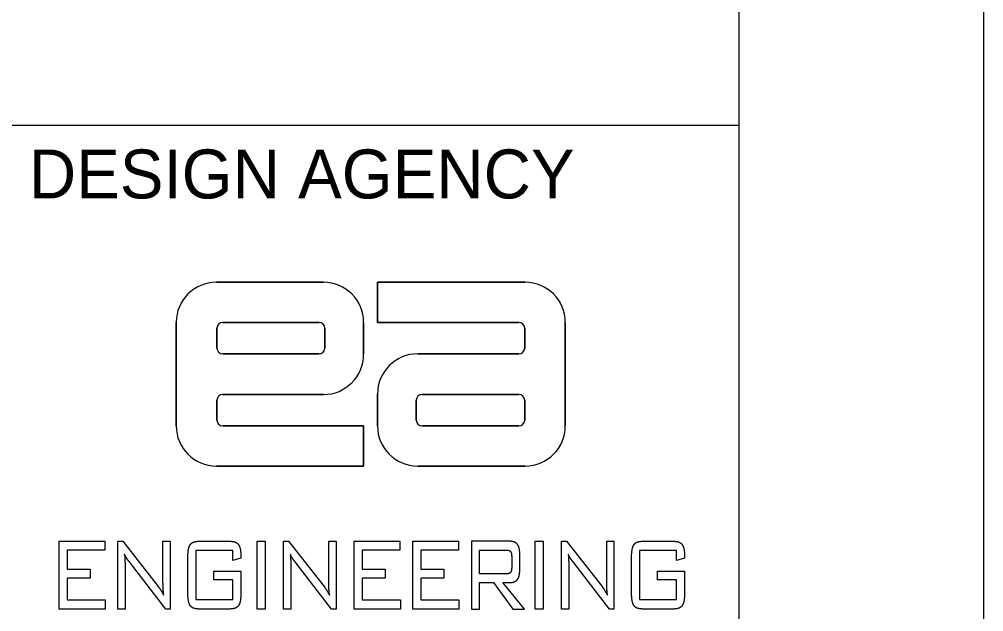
# Model space of a CAD drawing. Extents: x -15.1 to 34, y -7.8 to 43.8.
# Drawn here: x 32.03 to 34, y 3.506 to 4.716 of the extents above; entities that cross this region are included whole.
import ezdxf

# ---------------------------------------------------------------- set-up
doc = ezdxf.new("R2010")
doc.units = 0
for name, color, linetype in [('SH_Border', 7, 'Continuous'), ('SH_Cut_Line', 7, 'Continuous'), ('SH_Data', 7, 'Continuous'), ('TX_X_20', 7, 'Continuous')]:
    doc.layers.add(name, color=color, linetype=linetype)

msp = doc.modelspace()

# ---------------------------------------------------------------- linework, layer by layer
at = {"layer": 'SH_Border'}
msp.add_line((32, 4.5), (33.5, 4.5), dxfattribs=at)
msp.add_lwpolyline([(1.5, 21.5), (33.5, 21.5), (33.5, 0.5), (1.5, 0.5)], close=True, dxfattribs=at)
at = {"layer": 'SH_Cut_Line'}
msp.add_lwpolyline([(0, 0), (34, 0), (34, 22), (0, 22)], close=True, dxfattribs=at)
at = {"layer": 'TX_X_20'}
for p, q in [((32.6515, 4.1788), (32.433, 4.1788)), ((32.433, 4.1788), (32.6515, 4.1788)), ((32.762, 4.1788), (33.0635, 4.1788)), ((32.762, 4.0967), (32.762, 4.1788)), ((32.351, 4.0967), (32.351, 3.8852)), ((32.351, 3.8852), (32.351, 4.0967)), ((32.4459, 4.0967), (32.6426, 4.0967)), ((32.6426, 4.0967), (32.4459, 4.0967)), ((32.7336, 4.0315), (32.7336, 4.0967)), ((32.7336, 4.0967), (32.7336, 4.0315)), ((33.0507, 4.0967), (32.762, 4.0967)), ((33.1456, 3.8852), (33.1456, 4.0967)), ((33.1456, 4.0967), (33.1456, 3.8852)), ((32.434, 4.0444), (32.434, 4.0849)), ((32.434, 4.0849), (32.434, 4.0444)), ((32.6545, 4.0849), (32.6545, 4.0444)), ((32.6545, 4.0444), (32.6545, 4.0849)), ((33.0626, 4.0849), (33.0626, 4.0444)), ((33.0626, 4.0444), (33.0626, 4.0849)), ((32.6426, 4.0325), (32.4459, 4.0325)), ((32.4459, 4.0325), (32.6426, 4.0325)), ((33.0507, 4.0325), (32.8441, 4.0325)), ((32.8441, 4.0325), (33.0507, 4.0325)), ((32.4459, 3.9494), (32.6515, 3.9494)), ((32.6515, 3.9494), (32.4459, 3.9494)), ((32.762, 3.9504), (32.762, 3.8852)), ((32.762, 3.8852), (32.762, 3.9504)), ((32.853, 3.9494), (33.0507, 3.9494)), ((33.0507, 3.9494), (32.853, 3.9494)), ((32.434, 3.8971), (32.434, 3.9376)), ((32.434, 3.9376), (32.434, 3.8971)), ((32.8411, 3.8971), (32.8411, 3.9376)), ((32.8411, 3.9376), (32.8411, 3.8971)), ((33.0626, 3.9376), (33.0626, 3.8971)), ((33.0626, 3.8971), (33.0626, 3.9376)), ((32.4459, 3.8852), (32.7336, 3.8852)), ((32.7336, 3.8852), (32.7336, 3.8031)), ((33.0507, 3.8852), (32.853, 3.8852)), ((32.853, 3.8852), (33.0507, 3.8852)), ((32.7336, 3.8031), (32.433, 3.8031)), ((32.8441, 3.8031), (33.0635, 3.8031)), ((33.0635, 3.8031), (32.8441, 3.8031)), ((32.3975, 3.6495), (32.4602, 3.6495)), ((33.3037, 3.6495), (33.3663, 3.6495)), ((32.3748, 3.5439), (32.3748, 3.6168)), ((33.0361, 3.6173), (33.0361, 3.5971)), ((33.0526, 3.5917), (33.0526, 3.6227)), ((33.2809, 3.5439), (33.2809, 3.6168)), ((32.4602, 3.5111), (32.3975, 3.5111)), ((33.3663, 3.5111), (33.3037, 3.5111))]:
    msp.add_line(p, q, dxfattribs=at)
for points in [[(33.0635, 4.1788), (32.762, 4.1788), (32.762, 4.0967), (33.0507, 4.0967)], [(32.433, 3.8031), (32.7336, 3.8031), (32.7336, 3.8852), (32.4459, 3.8852)], [(32.2465, 3.5927), (32.2465, 3.5111), (32.2317, 3.5111), (32.2317, 3.6495), (32.2419, 3.6495), (32.3144, 3.5569)], [(32.3239, 3.5736), (32.3239, 3.6495), (32.3387, 3.6495), (32.3387, 3.5111), (32.3297, 3.5111), (32.2553, 3.6074)], [(32.5851, 3.5927), (32.5851, 3.5111), (32.5703, 3.5111), (32.5703, 3.6495), (32.5804, 3.6495), (32.6529, 3.5569)], [(32.6625, 3.5736), (32.6625, 3.6495), (32.6773, 3.6495), (32.6773, 3.5111), (32.6682, 3.5111), (32.5938, 3.6074)], [(33.032, 3.6495), (32.954, 3.6495), (32.954, 3.5111), (32.9702, 3.5111), (32.9702, 3.565), (32.9987, 3.565), (33.0381, 3.5111), (33.0621, 3.5111), (33.0178, 3.565), (33.032, 3.565)], [(33.1527, 3.5927), (33.1527, 3.5111), (33.1379, 3.5111), (33.1379, 3.6495), (33.148, 3.6495), (33.2205, 3.5569)], [(33.2301, 3.5736), (33.2301, 3.6495), (33.2449, 3.6495), (33.2449, 3.5111), (33.2358, 3.5111), (33.1614, 3.6074)], [(32.483, 3.6183), (32.483, 3.6149), (32.4668, 3.6103), (32.4668, 3.6307), (32.3909, 3.6307), (32.3909, 3.5304), (32.4668, 3.5304), (32.4668, 3.571), (32.4276, 3.571), (32.4276, 3.5886), (32.483, 3.5886), (32.483, 3.5439)], [(33.0257, 3.5829), (32.9702, 3.5829), (32.9702, 3.6316), (33.0257, 3.6316)], [(33.3891, 3.6183), (33.3891, 3.6149), (33.3729, 3.6103), (33.3729, 3.6307), (33.2971, 3.6307), (33.2971, 3.5304), (33.3729, 3.5304), (33.3729, 3.571), (33.3338, 3.571), (33.3338, 3.5886), (33.3891, 3.5886), (33.3891, 3.5439)]]:
    msp.add_lwpolyline(points, dxfattribs=at)
for points in [[(32.1121, 3.5111), (32.1121, 3.6495), (32.2053, 3.6495), (32.2053, 3.631), (32.1283, 3.631), (32.1283, 3.5925), (32.1754, 3.5925), (32.1754, 3.5742), (32.1283, 3.5742), (32.1283, 3.5301), (32.2061, 3.5301), (32.2061, 3.5111)], [(32.5166, 3.5111), (32.5166, 3.6495), (32.5329, 3.6495), (32.5329, 3.5111)], [(32.7147, 3.5111), (32.7147, 3.6495), (32.8079, 3.6495), (32.8079, 3.631), (32.7309, 3.631), (32.7309, 3.5925), (32.778, 3.5925), (32.778, 3.5742), (32.7309, 3.5742), (32.7309, 3.5301), (32.8087, 3.5301), (32.8087, 3.5111)], [(32.8343, 3.5111), (32.8343, 3.6495), (32.9276, 3.6495), (32.9276, 3.631), (32.8506, 3.631), (32.8506, 3.5925), (32.8977, 3.5925), (32.8977, 3.5742), (32.8506, 3.5742), (32.8506, 3.5301), (32.9283, 3.5301), (32.9283, 3.5111)], [(33.0842, 3.5111), (33.0842, 3.6495), (33.1005, 3.6495), (33.1005, 3.5111)]]:
    msp.add_lwpolyline(points, close=True, dxfattribs=at)
for centre, radius, start, end in [((32.433, 4.0967), 0.0821, 90, 180), ((32.433, 4.0967), 0.0821, 90, 180), ((32.6515, 4.0967), 0.0821, 0, 90), ((32.6515, 4.0967), 0.0821, 0, 90), ((33.0635, 4.0967), 0.0821, 0, 90), ((33.0635, 4.0967), 0.0821, 0, 90), ((32.4459, 4.0849), 0.0119, 90, 180), ((32.4459, 4.0849), 0.0119, 90, 180), ((32.6426, 4.0849), 0.0119, 0, 90), ((32.6426, 4.0849), 0.0119, 0, 90), ((33.0507, 4.0849), 0.0119, 0, 90), ((33.0507, 4.0849), 0.0119, 0, 90), ((32.4459, 4.0444), 0.0119, 180, 270), ((32.4459, 4.0444), 0.0119, 180, 270), ((32.6426, 4.0444), 0.0119, 270, 0), ((32.6426, 4.0444), 0.0119, 270, 0), ((33.0507, 4.0444), 0.0119, 270, 0), ((33.0507, 4.0444), 0.0119, 270, 0), ((32.6515, 4.0315), 0.0821, 270, 360), ((32.6515, 4.0315), 0.0821, 270, 360), ((32.8441, 3.9504), 0.0821, 90, 180), ((32.8441, 3.9504), 0.0821, 90, 180), ((32.4459, 3.9376), 0.0119, 90, 180), ((32.4459, 3.9376), 0.0119, 90, 180), ((32.853, 3.9376), 0.0119, 90, 180), ((32.853, 3.9376), 0.0119, 90, 180), ((33.0507, 3.9376), 0.0119, 0, 90), ((33.0507, 3.9376), 0.0119, 0, 90), ((32.433, 3.8852), 0.0821, 180, 270), ((32.433, 3.8852), 0.0821, 180, 270), ((32.4459, 3.8971), 0.0119, 180, 270), ((32.4459, 3.8971), 0.0119, 180, 270), ((32.8441, 3.8852), 0.0821, 180, 270), ((32.8441, 3.8852), 0.0821, 180, 270), ((32.853, 3.8971), 0.0119, 180, 270), ((32.853, 3.8971), 0.0119, 180, 270), ((33.0507, 3.8971), 0.0119, 270, 0), ((33.0507, 3.8971), 0.0119, 270, 0), ((33.0635, 3.8852), 0.0821, 270, 360), ((33.0635, 3.8852), 0.0821, 270, 360)]:
    msp.add_arc(centre, radius, start, end, dxfattribs=at)
for points in [[(32.3795, 3.6426), (32.3842, 3.6495), (32.3975, 3.6495)], [(32.4602, 3.6495), (32.4732, 3.6495), (32.4781, 3.6428)], [(33.0477, 3.6432), (33.0429, 3.6495), (33.032, 3.6495)], [(33.2857, 3.6426), (33.2904, 3.6495), (33.3037, 3.6495)], [(33.3663, 3.6495), (33.3794, 3.6495), (33.3842, 3.6428)], [(32.3748, 3.6168), (32.3748, 3.6356), (32.3795, 3.6426)], [(32.4781, 3.6428), (32.483, 3.636), (32.483, 3.6183)], [(33.0257, 3.6316), (33.0316, 3.6316), (33.0339, 3.6284)], [(33.0339, 3.6284), (33.0361, 3.6252), (33.0361, 3.6173)], [(33.0526, 3.6227), (33.0526, 3.6368), (33.0477, 3.6432)], [(33.2809, 3.6168), (33.2809, 3.6356), (33.2857, 3.6426)], [(33.3842, 3.6428), (33.3891, 3.636), (33.3891, 3.6183)], [(32.2536, 3.6094), (32.2481, 3.6165), (32.2454, 3.6229)], [(32.2454, 3.6229), (32.246, 3.6166), (32.2463, 3.6095)], [(32.2463, 3.6095), (32.2465, 3.6024), (32.2465, 3.5927)], [(32.2553, 3.6074), (32.2547, 3.608), (32.2536, 3.6094)], [(32.5921, 3.6094), (32.5866, 3.6165), (32.584, 3.6229)], [(32.584, 3.6229), (32.5845, 3.6166), (32.5848, 3.6095)], [(32.5848, 3.6095), (32.5851, 3.6024), (32.5851, 3.5927)], [(32.5938, 3.6074), (32.5932, 3.608), (32.5921, 3.6094)], [(33.1597, 3.6094), (33.1542, 3.6165), (33.1516, 3.6229)], [(33.1516, 3.6229), (33.1521, 3.6166), (33.1524, 3.6095)], [(33.1524, 3.6095), (33.1527, 3.6024), (33.1527, 3.5927)], [(33.1614, 3.6074), (33.1608, 3.608), (33.1597, 3.6094)], [(33.0339, 3.5861), (33.0317, 3.5829), (33.0257, 3.5829)], [(33.0361, 3.5971), (33.0361, 3.5892), (33.0339, 3.5861)], [(33.0477, 3.5714), (33.0526, 3.5777), (33.0526, 3.5917)], [(32.3243, 3.5535), (32.3239, 3.5607), (32.3239, 3.5736)], [(32.6628, 3.5535), (32.6625, 3.5607), (32.6625, 3.5736)], [(33.032, 3.565), (33.0429, 3.565), (33.0477, 3.5714)], [(33.2304, 3.5535), (33.2301, 3.5607), (33.2301, 3.5736)], [(32.3144, 3.5569), (32.3169, 3.5538), (32.3197, 3.5493)], [(32.3197, 3.5493), (32.3225, 3.5449), (32.3254, 3.5395)], [(32.3254, 3.5395), (32.3247, 3.5462), (32.3243, 3.5535)], [(32.6529, 3.5569), (32.6554, 3.5538), (32.6582, 3.5493)], [(32.6582, 3.5493), (32.661, 3.5449), (32.6639, 3.5395)], [(32.6639, 3.5395), (32.6632, 3.5462), (32.6628, 3.5535)], [(33.2205, 3.5569), (33.223, 3.5538), (33.2258, 3.5493)], [(33.2258, 3.5493), (33.2286, 3.5449), (33.2315, 3.5395)], [(33.2315, 3.5395), (33.2308, 3.5462), (33.2304, 3.5535)], [(32.3795, 3.5181), (32.3748, 3.525), (32.3748, 3.5439)], [(32.483, 3.5439), (32.483, 3.5249), (32.4782, 3.518)], [(33.2857, 3.5181), (33.2809, 3.525), (33.2809, 3.5439)], [(33.3891, 3.5439), (33.3891, 3.5249), (33.3843, 3.518)], [(32.3975, 3.5111), (32.3842, 3.5111), (32.3795, 3.5181)], [(32.4782, 3.518), (32.4734, 3.5111), (32.4602, 3.5111)], [(33.3037, 3.5111), (33.2904, 3.5111), (33.2857, 3.5181)], [(33.3843, 3.518), (33.3795, 3.5111), (33.3663, 3.5111)]]:
    msp.add_open_spline(points, degree=2, dxfattribs=at)

# ---------------------------------------------------------------- texts
at = {"layer": 'SH_Data'}
msp.add_text('DESIGN AGENCY', height=0.1, dxfattribs=at).set_placement((32.05, 4.35))

doc.saveas('drawing.dxf')
